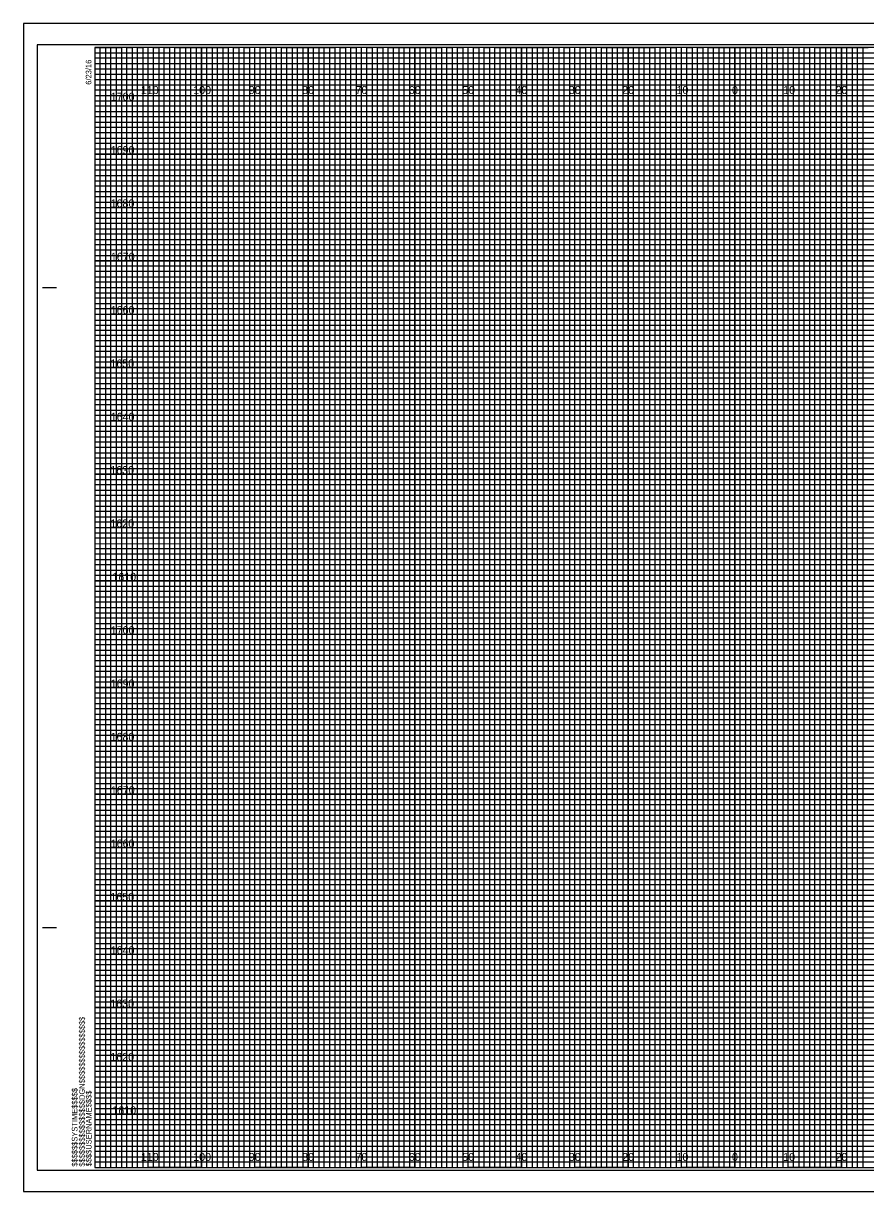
# Model space of a CAD drawing. Extents: x -13 to 1780, y -15 to 3284.
# Drawn here: x -13.4 to 144.5, y -4.5 to 214.5 of the extents above; entities that cross this region are included whole.
import ezdxf

# ---------------------------------------------------------------- set-up
doc = ezdxf.new("R2010")
doc.units = 0
for name, color, linetype in [('Prop Retaining Wall', 7, 'Continuous'), ('Prop SS Cut Line', 7, 'Continuous'), ('Prop SS Fill Line', 7, 'Continuous'), ('Prop SS Transition Line', 7, 'Continuous'), ('Prop XS Earthwork Shape', 7, 'Continuous'), ('Prop XS Noise Wall', 7, 'Continuous'), ('Prop XS Station Labels', 7, 'Continuous'), ('Raster_Level_0', 7, 'Continuous'), ('Scratch_Level_3', 7, 'Continuous'), ('Scratch_Level_7', 7, 'Continuous'), ('Typical Bridge Rail CELL', 7, 'Continuous')]:
    doc.layers.add(name, color=color, linetype=linetype)

msp = doc.modelspace()

# ---------------------------------------------------------------- linework, layer by layer
at = {"layer": 'Prop Retaining Wall'}
for p, q in [((-9.8, 165), (-7.3, 165)), ((-9.7, 165), (-7.2, 165)), ((-9.8, 45), (-7.3, 45)), ((-9.7, 45), (-7.2, 45)), ((0, 0), (0, 0)), ((0, 0), (0, 0)), ((0, 0), (0, 0)), ((0, 0), (0, 0)), ((0, 0), (0, 0)), ((0, 0), (0, 0)), ((0, 0), (0, 0))]:
    msp.add_line(p, q, dxfattribs=at)
msp.add_lwpolyline([(320, 210), (0, 210), (0, 0), (320, 0)], close=True, dxfattribs=at)
at = {"layer": 'Prop SS Cut Line'}
for points in [[(0, 210), (5, 210), (5, 0), (15, 0), (15, 210), (25, 210), (25, 0), (35, 0), (35, 210), (45, 210), (45, 0), (55, 0), (55, 210), (65, 210), (65, 0), (75, 0), (75, 210), (85, 210), (85, 0), (95, 0), (95, 210), (105, 210), (105, 0), (115, 0), (115, 210), (125, 210), (125, 0), (135, 0), (135, 210), (145, 210)], [(0, 205), (275, 205)], [(0, 185), (320, 185), (320, 195), (0, 195)], [(0, 165), (320, 165), (320, 175), (0, 175)], [(0, 145), (320, 145), (320, 155), (0, 155)], [(0, 125), (320, 125), (320, 135), (0, 135)], [(0, 105), (320, 105), (320, 115), (0, 115)], [(0, 85), (320, 85), (320, 95), (0, 95)], [(0, 65), (320, 65), (320, 75), (0, 75)], [(0, 45), (320, 45), (320, 55), (0, 55)], [(0, 25), (320, 25), (320, 35), (0, 35)], [(0, 5), (320, 5), (320, 15), (0, 15)]]:
    msp.add_lwpolyline(points, dxfattribs=at)
at = {"layer": 'Prop SS Fill Line'}
for p, q in [((10, 210), (0, 210)), ((10, 0), (10, 210)), ((30, 210), (20, 210)), ((20, 210), (20, 0)), ((30, 0), (30, 210)), ((50, 210), (40, 210)), ((40, 210), (40, 0)), ((50, 0), (50, 210)), ((70, 210), (60, 210)), ((60, 210), (60, 0)), ((70, 0), (70, 210)), ((90, 210), (80, 210)), ((80, 210), (80, 0)), ((90, 0), (90, 210)), ((110, 210), (100, 210)), ((100, 210), (100, 0)), ((110, 0), (110, 210)), ((130, 210), (120, 210)), ((120, 210), (120, 0)), ((130, 0), (130, 210)), ((150, 210), (140, 210)), ((140, 210), (140, 0)), ((20, 0), (10, 0)), ((40, 0), (30, 0)), ((60, 0), (50, 0)), ((80, 0), (70, 0)), ((100, 0), (90, 0)), ((120, 0), (110, 0)), ((140, 0), (130, 0))]:
    msp.add_line(p, q, dxfattribs=at)
for points in [[(0, 200), (320, 200), (320, 190), (0, 190)], [(0, 180), (320, 180), (320, 170), (0, 170)], [(0, 160), (320, 160), (320, 150), (0, 150)], [(0, 140), (320, 140), (320, 130), (0, 130)], [(0, 120), (320, 120), (320, 110), (0, 110)], [(0, 100), (320, 100), (320, 90), (0, 90)], [(0, 80), (320, 80), (320, 70), (0, 70)], [(0, 60), (320, 60), (320, 50), (0, 50)], [(0, 40), (320, 40), (320, 30), (0, 30)], [(0, 20), (320, 20), (320, 10), (0, 10)]]:
    msp.add_lwpolyline(points, dxfattribs=at)
at = {"layer": 'Prop SS Transition Line'}
for p, q in [((0, 209), (260, 209)), ((260, 207.98), (0, 207.98)), ((0, 207.98), (0, 207)), ((0, 207), (260, 207)), ((260, 205.89), (0, 205.89)), ((0, 205.89), (0, 204)), ((0, 204), (320, 204))]:
    msp.add_line(p, q, dxfattribs=at)
for points in [[(0, 203), (270, 203), (320, 203), (320, 202), (0, 202)], [(0, 201), (320, 201), (320, 199), (0, 199)], [(0, 198), (320, 198), (320, 197), (0, 196.98)], [(0, 196), (320, 196), (320, 194), (0, 194)], [(0, 193), (320, 193), (320, 192), (0, 192)], [(0, 191), (320, 191), (320, 189), (0, 189)], [(0, 188), (320, 188), (320, 187), (0, 187)], [(0, 186), (320, 186), (320, 184), (0, 184)], [(0, 183), (320, 183), (320, 182), (0, 182)], [(0, 181), (320, 181), (320, 179), (0, 179)], [(0, 178), (320, 178), (320, 177), (0, 177)], [(0, 176), (320, 176), (320, 173.95), (320, 173), (320, 172), (0, 172)], [(0, 174), (320, 174), (320, 173), (0, 173)], [(0, 171), (320, 171), (320, 169), (0, 169.03)], [(0, 169.03), (320, 169), (320, 168), (0, 168)], [(0, 167), (320, 167), (320, 166), (0, 166)], [(0, 164), (320, 164), (320, 163), (0, 163)], [(0, 162), (320, 162), (320, 161), (0, 161)], [(-0.07, 158.89), (320, 158.89), (320, 157.88), (-0.07, 157.88)], [(0, 157), (320, 157), (320, 156), (0, 156)], [(0, 154), (320, 154), (320, 153), (0, 153)], [(0, 152), (320, 152), (320, 151), (0, 151)], [(0, 149), (320, 149), (320, 148), (0, 148)], [(0, 147), (320, 147), (320, 146), (0, 146)], [(0, 144), (320, 144), (320, 143), (0, 143)], [(0, 142), (320, 142), (320, 141), (0, 141)], [(0, 139), (320, 139), (319.99, 137.98), (0, 138)], [(0, 137), (320, 137), (320, 136), (0, 136)], [(0, 134), (320, 134), (320, 133), (0, 133)], [(0, 132), (320, 132), (320, 131), (0, 131)], [(0, 129), (320, 129), (320, 128), (0, 128)], [(0, 127), (320, 127), (320, 126), (0, 126)], [(0, 124), (320, 124), (320, 123), (0, 123)], [(0, 122), (320, 122), (320, 121), (0, 121)], [(0, 119), (320, 119), (320, 118), (0, 118)], [(0, 116.99), (320.07, 116.91), (320, 116), (0, 116)], [(0, 114), (320, 114), (320, 113), (0, 113)], [(0, 112), (320, 112), (320, 111), (0, 111)], [(0, 109), (320, 109), (320, 108), (0, 108)], [(0, 107), (320, 107), (320, 106), (0, 106)], [(0, 104), (320, 104), (320, 103), (0, 103)], [(0, 102), (320, 102), (320, 101), (0, 101)], [(0, 99), (320, 99), (320, 98), (0, 98)], [(0, 97), (320, 97), (320, 96), (0, 96)], [(0, 94), (320, 94), (320, 93), (0, 93)], [(0, 92), (320, 92), (320, 91), (0, 91)], [(0, 89), (320, 89), (320, 88), (0, 88)], [(0, 87), (320, 87), (320, 86), (0, 86)], [(0, 84), (320, 84), (320, 83), (0, 83)], [(0, 82), (320, 82), (320, 81), (0, 81)], [(0, 79), (320, 79), (319.99, 77.98), (0, 78)], [(0, 77), (320, 77), (320, 76), (0, 76)], [(0, 74), (320, 74), (320, 73), (0, 73)], [(0, 72), (320, 72), (320, 71), (0, 71)], [(0, 69), (320, 69), (320, 68), (0, 68)], [(0, 67), (320, 67), (320, 66), (0, 66)], [(0, 64), (320, 64), (320, 63), (0, 63)], [(0, 62), (320, 62), (320, 61), (0, 61)], [(0, 59), (320, 59), (320, 58), (0, 58)], [(0, 56.99), (320.07, 56.91), (320, 56), (0, 56)], [(0, 54), (320, 54), (320, 53), (0, 53)], [(0, 52), (320, 52), (320, 51), (0, 51)], [(0, 49), (320, 49), (320, 48), (0, 48)], [(0, 47), (320, 47), (320, 46), (0, 46)], [(0, 44), (320, 44), (320, 43), (0, 43)], [(0, 42), (320, 42), (320, 41), (0, 41)], [(0, 39), (320, 39), (320, 38), (0, 38)], [(0, 37), (320, 37), (320, 36), (0, 36)], [(0, 34), (320, 34), (320, 33), (0, 33)], [(0, 32), (320, 32), (320, 31), (0, 31)], [(0, 29), (320, 29), (320, 28), (0, 28)], [(0, 27), (320, 27), (320, 26), (0, 26)], [(0, 24), (320, 24), (320, 23), (0, 23)], [(0, 22), (320, 22), (320, 21), (0, 21)], [(0, 19), (320, 19), (320, 18), (0, 18)], [(0, 17), (320, 17), (320, 16), (0, 16)], [(0, 14), (320, 14), (320, 13), (0, 13)], [(0, 12), (320, 12), (320, 11), (0, 11)], [(0, 9), (320, 9), (320, 8), (0, 8)], [(0, 7), (320, 7), (320, 6), (0, 6)], [(0, 4), (320, 4), (320, 3), (0, 3)], [(0, 2), (320, 2), (320, 1), (0, 1)]]:
    msp.add_lwpolyline(points, dxfattribs=at)
at = {"layer": 'Prop XS Earthwork Shape'}
msp.add_lwpolyline([(-13.4, -4.5), (323.3, -4.5), (323.3, 214.5), (-13.4, 214.5)], close=True, dxfattribs=at)
at = {"layer": 'Prop XS Noise Wall'}
for p, q in [((10, 0), (10, 210)), ((20, 0), (20, 210)), ((30, 0), (30, 210)), ((40, 0), (40, 210)), ((50, 0), (50, 210)), ((60, 0), (60, 210)), ((70, 0), (70, 210)), ((80, 0), (80, 210)), ((90, 0), (90, 210)), ((100, 0), (100, 210)), ((110, 0), (110, 210)), ((120, 0), (120, 210)), ((130, 0), (130, 210)), ((140, 0), (140, 210)), ((0, 200), (320, 200)), ((0, 190), (320, 190)), ((0, 180), (320, 180)), ((0, 170), (320, 170)), ((0, 160), (320, 160)), ((0, 150), (320, 150)), ((0, 140), (320, 140)), ((0, 130), (320, 130)), ((0, 120), (320, 120)), ((0, 110), (320, 110)), ((0, 100), (320, 100)), ((0, 90), (320, 90)), ((0, 80), (320, 80)), ((0, 70), (320, 70)), ((0, 60), (320, 60)), ((0, 50), (320, 50)), ((0, 40), (320, 40)), ((0, 30), (320, 30)), ((0, 20), (320, 20)), ((0, 10), (320, 10))]:
    msp.add_line(p, q, dxfattribs=at)
at = {"layer": 'Prop XS Station Labels'}
for p, q in [((323.3, 214.5), (-13.4, 214.5)), ((-13.4, 214.5), (-13.4, -4.5)), ((-13.4, -4.5), (323.3, -4.5))]:
    msp.add_line(p, q, dxfattribs=at)
at = {"layer": 'Scratch_Level_7'}
msp.add_lwpolyline([(-10.8, -0.5), (322.4, -0.5), (322.4, 210.5), (-10.8, 210.5)], close=True, dxfattribs=at)
at = {"layer": 'Typical Bridge Rail CELL'}
for points in [[(0, 0), (1, 0), (1, 210), (2, 210), (2, 0)], [(2, 0), (3, 0), (3, 210), (4, 210), (4, 0)], [(5, 0), (6, 0), (6, 210), (7, 210), (7, 0)], [(7, 0), (8, 0), (8, 210), (9, 210), (9, 0)], [(10, 0), (11, 0), (11, 210), (12, 210), (12, 0)], [(12, 0), (13, 0), (13, 210), (14, 210), (14, 0)], [(15, 0), (16, 0), (16, 210), (17, 210), (17, 0)], [(17, 0), (18, 0), (18, 210), (19, 210), (19, 0)], [(20, 0), (21, 0), (21, 210), (22, 210), (22, 0)], [(22, 0), (23, 0), (23, 210), (24, 210), (24, 0)], [(25, 0), (26, 0), (26, 210), (27, 210), (27, 0)], [(27, 0), (28, 0), (28, 210), (29, 210), (29, 0)], [(30, 0), (31, 0), (31, 210), (32, 210), (32, 0)], [(32, 0), (33, 0), (33, 210), (34, 210), (34, 0)], [(35, 0), (36, 0), (36, 210), (37, 210), (37, 0)], [(37, 0), (38, 0), (38, 210), (39, 210), (39, 0)], [(40, 0), (41, 0), (41, 210), (42, 210), (42, 0)], [(42, 0), (43, 0), (43, 210), (44, 210), (44, 0)], [(45, 0), (46, 0), (46, 210), (47, 210), (47, 0)], [(47, 0), (48, 0), (48, 210), (49, 210), (49, 0)], [(50, 0), (51, 0), (51, 210), (52, 210), (52, 0)], [(52, 0), (53, 0), (53, 210), (54, 210), (54, 0)], [(55, 0), (56, 0), (56, 210), (57, 210), (57, 0)], [(57, 0), (58, 0), (58, 210), (59, 210), (59, 0)], [(60, 0), (61, 0), (61, 210), (62, 210), (62, 0)], [(62, 0), (63, 0), (63, 210), (64, 210), (64, 0)], [(65, 0), (66, 0), (66, 210), (67, 210), (67, 0)], [(67, 0), (68, 0), (68, 210), (69, 210), (69, 0)], [(70, 0), (71, 0), (71, 210), (72, 210), (72, 0)], [(72, 0), (73, 0), (73, 210), (74, 210), (74, 0)], [(75, 0), (76, 0), (76, 210), (77, 210), (77, 0)], [(77, 0), (78, 0), (78, 210), (79, 210), (79, 0)], [(80, 0), (81, 0), (81, 210), (82, 210), (82, 0)], [(82, 0), (83, 0), (83, 210), (84, 210), (84, 0)], [(85, 0), (86, 0), (86, 210), (87, 210), (87, 0)], [(87, 0), (88, 0), (88, 210), (89, 210), (89, 0)], [(90, 0), (91, 0), (91, 210), (92, 210), (92, 0)], [(92, 0), (93, 0), (93, 210), (94, 210), (94, 0)], [(95, 0), (96, 0), (96, 210), (97, 210), (97, 0)], [(97, 0), (98, 0), (98, 210), (99, 210), (99, 0)], [(100, 0), (101, 0), (101, 210), (102, 210), (102, 0)], [(102, 0), (103, 0), (103, 210), (104, 210), (104, 0)], [(105, 0), (106, 0), (106, 210), (107, 210), (107, 0)], [(107, 0), (108, 0), (108, 210), (109, 210), (109, 0)], [(110, 0), (111, 0), (111, 210), (112, 210), (112, 0)], [(112, 0), (113, 0), (113, 210), (114, 210), (114, 0)], [(115, 0), (116, 0), (116, 210), (117, 210), (117, 0)], [(117, 0), (118, 0), (118, 210), (119, 210), (119, 0)], [(120, 0), (121, 0), (121, 210), (122, 210), (122, 0)], [(122, 0), (123, 0), (123, 210), (124, 210), (124, 0)], [(125, 0), (126, 0), (126, 210), (127, 210), (127, 0)], [(127, 0), (128, 0), (128, 210), (129, 210), (129, 0)], [(130, 0), (131, 0), (131, 210), (132, 210), (132, 0)], [(132, 0), (133, 0), (133, 210), (134, 210), (134, 0)], [(135, 0), (136, 0), (136, 210), (137, 210), (137, 0)], [(137, 0), (138, 0), (138, 210), (139, 210), (139, 0)], [(140, 0), (141, 0), (141, 210), (142, 210), (142, 0)], [(142, 0), (143, 0), (143, 210), (144, 210), (144, 0)]]:
    msp.add_lwpolyline(points, dxfattribs=at)

# ---------------------------------------------------------------- texts
at = {"layer": 'Prop Retaining Wall'}
for s, p in [('6/23/16', (-0.65, 203)), ('$$$$$$$$$$$$$$$$DGN$$$$$$$$$$$$$$$$', (-1.88, 0.18)), ('$$$$$$SYSTIME$$$$$', (-3.26, 0.18)), ('$$$$USERNAME$$$$', (-0.62, 0.23))]:
    msp.add_text(s, height=1.05, rotation=90, dxfattribs=at).set_placement(p)
at = {"layer": 'Raster_Level_0'}
for s, p in [('110', (8.62, 201.25)), ('100', (18.44, 201.25)), ('90', (28.86, 201.25)), ('80', (38.86, 201.25)), ('70', (48.86, 201.25)), ('60', (58.86, 201.25)), ('50', (68.86, 201.25)), ('40', (78.86, 201.25)), ('30', (88.86, 201.25)), ('20', (98.86, 201.25)), ('10', (109.04, 201.25)), ('0', (119.45, 201.25)), ('0', (119.45, 201.25)), ('10', (129.04, 201.25)), ('20', (138.86, 201.25)), ('110', (8.62, 1.25)), ('100', (18.44, 1.25)), ('90', (28.86, 1.25)), ('80', (38.86, 1.25)), ('70', (48.86, 1.25)), ('60', (58.86, 1.25)), ('50', (68.86, 1.25)), ('40', (78.86, 1.25)), ('30', (88.86, 1.25)), ('20', (98.86, 1.25)), ('10', (109.04, 1.25)), ('0', (119.45, 1.25)), ('0', (119.45, 1.25)), ('10', (129.04, 1.25)), ('20', (138.86, 1.25))]:
    msp.add_text(s, height=1.5, dxfattribs=at).set_placement(p)
at = {"layer": 'Scratch_Level_3'}
for s, p in [('1700', (2.98, 200)), ('1690', (2.97, 190)), ('1680', (2.95, 180)), ('1670', (3, 170)), ('1660', (2.97, 160)), ('1650', (2.92, 150)), ('1640', (2.97, 140)), ('1630', (2.89, 130)), ('1620', (2.9, 120)), ('1610', (3.28, 110)), ('1700', (2.98, 100)), ('1690', (2.97, 90)), ('1680', (2.95, 80)), ('1670', (3, 70)), ('1660', (2.97, 60)), ('1650', (2.92, 50)), ('1640', (2.97, 40)), ('1630', (2.89, 30)), ('1620', (2.9, 20)), ('1610', (3.28, 10))]:
    msp.add_text(s, height=1.5, dxfattribs=at).set_placement(p)

doc.saveas('drawing.dxf')
